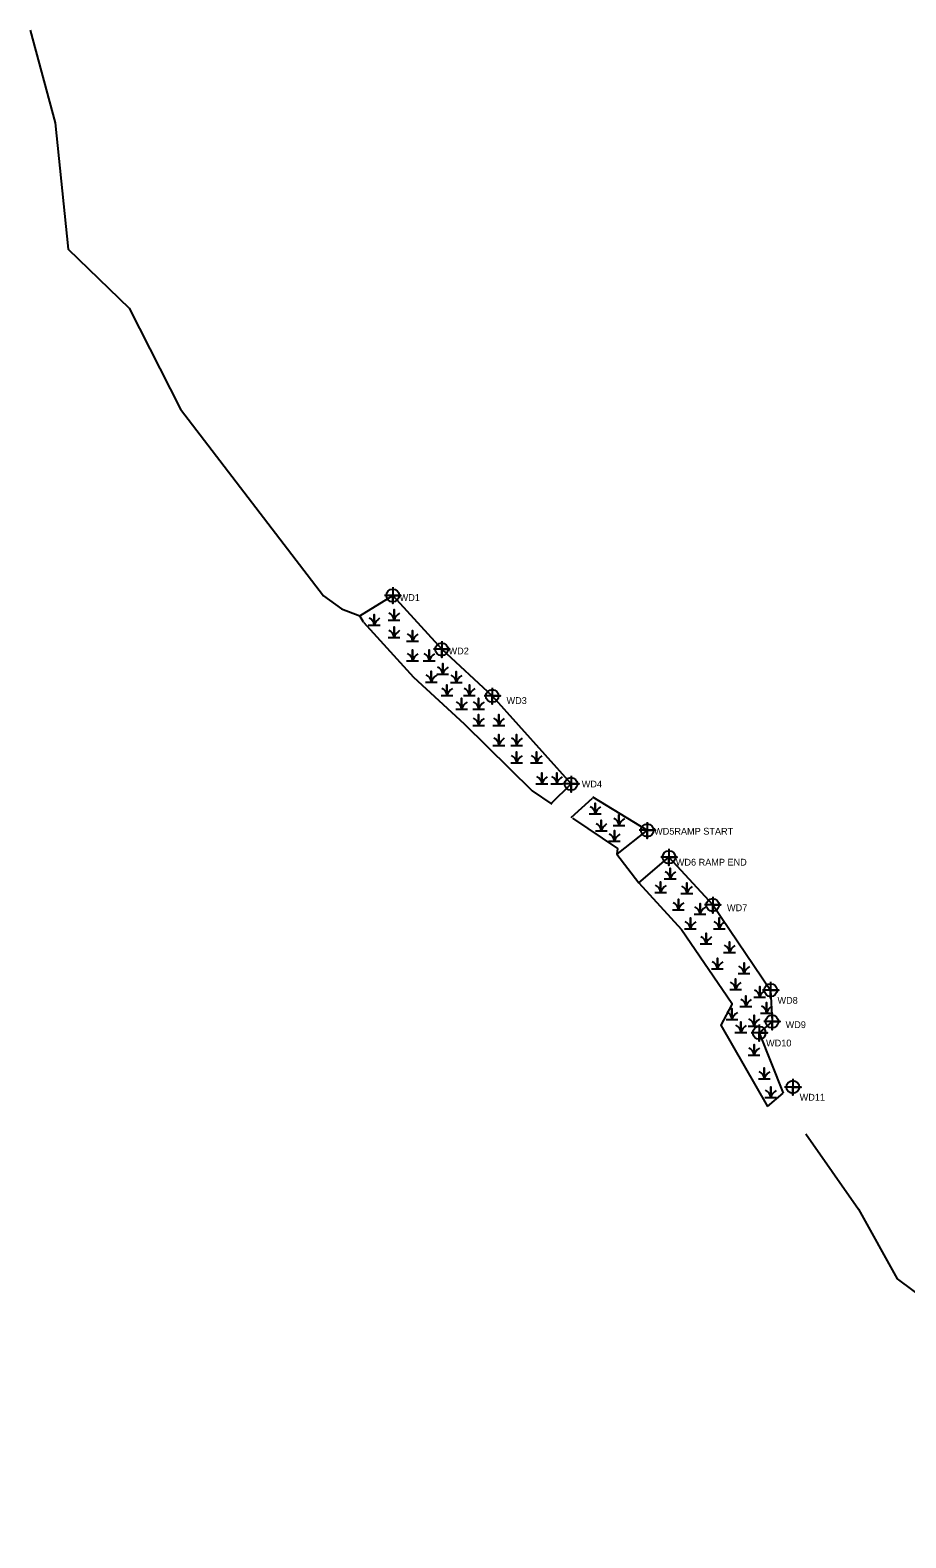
# Model space of a CAD drawing. Extents: x 2603618 to 2605510, y 618189 to 619022.
# Drawn here: x 2604554 to 2604875, y 618469 to 619022 of the extents above; entities that cross this region are included whole.
import ezdxf

# ---------------------------------------------------------------- set-up
doc = ezdxf.new("R2010")
doc.units = 0
for name, color, linetype in [('Exist Environmental Wetland Boundary', 7, 'Continuous'), ('Exist Environmental Wetland Boundary Cogo Comment', 7, 'Continuous'), ('Exist Environmental Wetland Boundary Cogo Point CELL', 7, 'Continuous'), ('Exist Hydro Jurisdictional Stream or Body of Water Mitigable', 7, 'Continuous'), ('Exist Hydro Swamp or Marsh', 7, 'Continuous')]:
    doc.layers.add(name, color=color, linetype=linetype)

# ---------------------------------------------------------------- blocks, each defined once
blk = doc.blocks.new('Exist Hydro Swamp or Marsh')
at = {"layer": 'Exist Hydro Swamp or Marsh'}
blk.add_line((0, 0), (0, 0), dxfattribs=at)
blk.add_lwpolyline([(-0.043, -0.036), (0, -0.036), (0, 0.043), (0, -0.036), (0.043, -0.036)], dxfattribs=at)
for centre, radius, start, end in [((-0.061, -0.04), 0.0615, 4.1403, 67.535), ((0.091, -0.066), 0.0961, 122.1274, 161.6222)]:
    blk.add_arc(centre, radius, start, end, dxfattribs=at)

msp = doc.modelspace()

# ---------------------------------------------------------------- linework, layer by layer
at = {"layer": 'Exist Environmental Wetland Boundary'}
for p, q in [((2604752.58, 618745.6), (2604745.03, 618738.23)), ((2604752.58, 618733.29), (2604760.4, 618740.37)), ((2604780.51, 618728.6), (2604769.4, 618719.83)), ((2604777.48, 618709.33), (2604788.46, 618718.76)), ((2604824.56, 618627.41), (2604830.26, 618632.34))]:
    msp.add_line(p, q, dxfattribs=at)
for points in [[(2604676.6, 618804.93), (2604675.26, 618807.25), (2604687.3, 618814.66)], [(2604687.3, 618814.66), (2604705.22, 618794.93), (2604723.72, 618777.84), (2604752.58, 618745.6)], [(2604676.6, 618804.93), (2604694.94, 618784.74), (2604713.4, 618767.68), (2604738.35, 618743.08), (2604745.6, 618738.18)], [(2604760.4, 618740.84), (2604780.51, 618728.6)], [(2604753.07, 618733.11), (2604769.55, 618721.96), (2604769.4, 618719.83)], [(2604788.46, 618718.76), (2604804.47, 618701.24), (2604825.7, 618670.04), (2604826.2, 618658.54), (2604821.51, 618654.4), (2604830.26, 618632.34)], [(2604777.48, 618709.33), (2604793.1, 618692.25), (2604811.43, 618665.3), (2604811.45, 618664.82), (2604807.5, 618657.17), (2604824.56, 618627.41)]]:
    msp.add_lwpolyline(points, dxfattribs=at)
at = {"layer": 'Exist Environmental Wetland Boundary Cogo Point CELL'}
for points in [[(2604687.3, 618817.66), (2604687.3, 618811.66), (2604687.3, 618814.66), (2604690.3, 618814.66), (2604684.3, 618814.66)], [(2604705.22, 618797.93), (2604705.22, 618791.93), (2604705.22, 618794.93), (2604708.22, 618794.93), (2604702.22, 618794.93)], [(2604723.72, 618780.84), (2604723.72, 618774.84), (2604723.72, 618777.84), (2604726.72, 618777.84), (2604720.72, 618777.84)], [(2604752.58, 618748.6), (2604752.58, 618742.6), (2604752.58, 618745.6), (2604755.58, 618745.6), (2604749.58, 618745.6)], [(2604780.51, 618731.6), (2604780.51, 618725.6), (2604780.51, 618728.6), (2604783.51, 618728.6), (2604777.51, 618728.6)], [(2604788.46, 618721.76), (2604788.46, 618715.76), (2604788.46, 618718.76), (2604791.46, 618718.76), (2604785.46, 618718.76)], [(2604804.47, 618704.24), (2604804.47, 618698.24), (2604804.47, 618701.24), (2604807.47, 618701.24), (2604801.47, 618701.24)], [(2604825.7, 618673.04), (2604825.7, 618667.04), (2604825.7, 618670.04), (2604828.7, 618670.04), (2604822.7, 618670.04)], [(2604821.51, 618657.4), (2604821.51, 618651.4), (2604821.51, 618654.4), (2604824.51, 618654.4), (2604818.51, 618654.4)], [(2604826.2, 618661.54), (2604826.2, 618655.54), (2604826.2, 618658.54), (2604829.2, 618658.54), (2604823.2, 618658.54)], [(2604833.82, 618637.54), (2604833.82, 618631.54), (2604833.82, 618634.54), (2604836.82, 618634.54), (2604830.82, 618634.54)]]:
    msp.add_lwpolyline(points, dxfattribs=at)
for centre in [(2604687.3, 618814.66), (2604705.22, 618794.93), (2604723.72, 618777.84), (2604752.58, 618745.6), (2604780.51, 618728.6), (2604788.46, 618718.76), (2604804.47, 618701.24), (2604825.7, 618670.04), (2604821.51, 618654.4), (2604826.2, 618658.54), (2604833.82, 618634.54)]:
    msp.add_circle(centre, 2.34, dxfattribs=at)
at = {"layer": 'Exist Hydro Jurisdictional Stream or Body of Water Mitigable'}
msp.add_line((2604769.4, 618719.83), (2604777.48, 618709.33), dxfattribs=at)
for points in [[(2604554.49, 619021.8), (2604563.61, 618987.79), (2604568.44, 618941.54), (2604590.76, 618919.9), (2604609.6, 618882.91), (2604661.91, 618814.52), (2604668.52, 618809.81), (2604675.26, 618807.25)], [(2604838.54, 618617.4), (2604857.9, 618589.82), (2604872.03, 618564.3), (2604889.79, 618551.08), (2604911.66, 618521.46), (2604943.55, 618486.13), (2604958.7, 618469.35)]]:
    msp.add_lwpolyline(points, dxfattribs=at)

# ---------------------------------------------------------------- block references
at = {"layer": 'Exist Hydro Swamp or Marsh', "xscale": 50, "yscale": 50}
for p in [(2604680.47, 618805.52), (2604687.76, 618807.38), (2604687.76, 618801), (2604694.53, 618799.7), (2604694.53, 618792.54), (2604700.64, 618792.54), (2604705.59, 618787.59), (2604701.42, 618784.72), (2604710.54, 618784.59), (2604707.15, 618779.78), (2604715.35, 618779.78), (2604712.49, 618774.83), (2604718.74, 618774.83), (2604718.74, 618768.84), (2604726.15, 618768.84), (2604726.15, 618761.54), (2604732.66, 618761.54), (2604732.66, 618755.16), (2604739.95, 618755.16), (2604741.9, 618747.48), (2604747.37, 618747.48), (2604761.43, 618736.41), (2604770.15, 618732.11), (2604763.64, 618730.16), (2604768.46, 618726.38), (2604788.89, 618712.58), (2604785.38, 618707.63), (2604795.01, 618707.24), (2604791.89, 618701.25), (2604799.83, 618699.69), (2604796.31, 618694.35), (2604806.86, 618694.35), (2604802.04, 618688.75), (2604810.63, 618685.62), (2604806.2, 618679.63), (2604815.97, 618677.94), (2604812.84, 618672.08), (2604816.62, 618665.83), (2604821.69, 618669.22), (2604811.54, 618661.14), (2604824.17, 618663.36), (2604814.79, 618656.32), (2604819.61, 618658.67), (2604819.61, 618647.99), (2604823.38, 618639.39), (2604825.73, 618632.49)]:
    msp.add_blockref('Exist Hydro Swamp or Marsh', p, dxfattribs=at)

# ---------------------------------------------------------------- texts
at = {"layer": 'Exist Environmental Wetland Boundary Cogo Comment'}
for s, p in [('WD1', (2604689.8, 618812.65)), ('WD2', (2604707.72, 618793.06)), ('WD3', (2604728.96, 618774.9)), ('WD4', (2604756.51, 618744.3)), ('WD5RAMP START', (2604783.01, 618727.01)), ('WD6 RAMP END', (2604790.96, 618715.68)), ('WD7', (2604809.71, 618698.97)), ('WD8', (2604828.2, 618665.04)), ('WD9', (2604831.18, 618656.14)), ('WD10', (2604824.01, 618649.4)), ('WD11', (2604836.32, 618629.55))]:
    msp.add_text(s, height=2.5, dxfattribs=at).set_placement(p)

doc.saveas('drawing.dxf')
